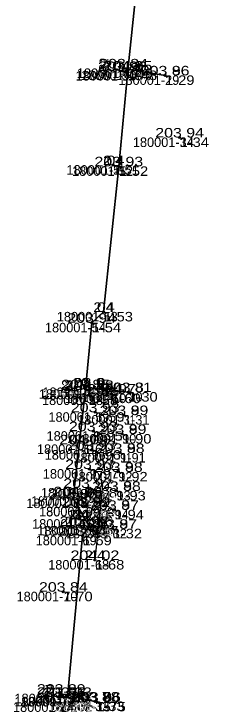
# Model space of a CAD drawing. Extents: x -598473 to -594209, y -1163589 to -1162143.
# Drawn here: x -598473.2 to -598440.8, y -1162504.8 to -1162394.8 of the extents above; entities that cross this region are included whole.
import ezdxf
from ezdxf.enums import TextEntityAlignment as Align

# ---------------------------------------------------------------- set-up
doc = ezdxf.new("R2010")
doc.units = 0
doc.header["$LTSCALE"] = 0.6
doc.header["$PDMODE"] = 32
doc.header["$PDSIZE"] = 0.3
doc.layers.add('1', color=7, linetype='Continuous', lineweight=35)
doc.layers.add('60', color=7, linetype='Continuous', lineweight=25)
for name, color, linetype in [('57', 7, 'Continuous'), ('58', 7, 'Continuous'), ('59', 7, 'Continuous'), ('61', 7, 'Continuous'), ('62', 7, 'Continuous')]:
    doc.layers.add(name, color=color, linetype=linetype)

msp = doc.modelspace()

# ---------------------------------------------------------------- linework, layer by layer
at = {"layer": '1'}
for p, q in [((-598455.95, -1162403.34), (-598449.41, -1162404.44)), ((-598455.28, -1162403.68), (-598456.15, -1162403.75)), ((-598461.93, -1162453.93), (-598461.34, -1162454.04)), ((-598461.36, -1162453.65), (-598455.2, -1162454.38)), ((-598465.77, -1162501.93), (-598460.42, -1162503.16)), ((-598465.77, -1162502.43), (-598464.78, -1162502.45))]:
    msp.add_line(p, q, dxfattribs=at)
for points in [[(-598441.41, -1162294.39), (-598440.77, -1162295.32), (-598444.43, -1162309.35), (-598448.01, -1162329.58), (-598450.14, -1162351.55), (-598449.54, -1162355.6), (-598452.26, -1162382.21), (-598452.85, -1162386.89), (-598453.59, -1162387.55), (-598455.28, -1162403.68), (-598456.7, -1162418.78), (-598459.1, -1162441.73), (-598460.97, -1162443.45), (-598461.93, -1162453.93), (-598463.91, -1162471.16), (-598461.39, -1162475.51), (-598462.43, -1162477.03), (-598464.78, -1162502.45), (-598464.78, -1162502.45)], [(-598461.472, -1162453.735), (-598461.447, -1162453.537), (-598461.249, -1162453.563), (-598461.274, -1162453.761)]]:
    msp.add_lwpolyline(points, dxfattribs=at)
for points in [[(-598455.864, -1162403.451), (-598456.062, -1162403.425), (-598456.037, -1162403.227), (-598455.839, -1162403.253)], [(-598456.064, -1162403.861), (-598456.262, -1162403.835), (-598456.237, -1162403.637), (-598456.039, -1162403.663)], [(-598449.508, -1162404.322), (-598449.31, -1162404.348), (-598449.335, -1162404.546), (-598449.533, -1162404.52)], [(-598461.254, -1162454.151), (-598461.452, -1162454.125), (-598461.427, -1162453.927), (-598461.229, -1162453.953)], [(-598455.295, -1162454.28), (-598455.097, -1162454.306), (-598455.122, -1162454.504), (-598455.32, -1162454.478)], [(-598465.684, -1162502.041), (-598465.882, -1162502.015), (-598465.857, -1162501.817), (-598465.659, -1162501.843)], [(-598465.684, -1162502.541), (-598465.882, -1162502.515), (-598465.857, -1162502.317), (-598465.659, -1162502.343)], [(-598460.513, -1162503.034), (-598460.315, -1162503.06), (-598460.34, -1162503.258), (-598460.538, -1162503.232)]]:
    msp.add_lwpolyline(points, close=True, dxfattribs=at)
msp.add_point((-598458.553, -1162454.51), dxfattribs=at)
at = {"layer": '60'}
msp.add_line((-598459.294, -1162469.09), (-598460.46, -1162480.85), dxfattribs=at)
for p in [(-598456.15, -1162403.75), (-598455.95, -1162403.34), (-598455.28, -1162403.68), (-598449.41, -1162404.44), (-598447.13, -1162414.23), (-598457.58, -1162418.59), (-598456.7, -1162418.78), (-598459.1, -1162441.73), (-598460.97, -1162443.45), (-598461.93, -1162453.93), (-598461.36, -1162453.65), (-598461.34, -1162454.04), (-598455.2, -1162454.38), (-598461.44, -1162454.91), (-598457.86, -1162454.616), (-598460.42, -1162457.55), (-598455.89, -1162458), (-598460.715, -1162460.537), (-598456.187, -1162460.988), (-598462.23, -1162462.62), (-598461.01, -1162463.523), (-598456.483, -1162463.977), (-598461.305, -1162466.51), (-598456.78, -1162466.965), (-598461.6, -1162469.497), (-598463.17, -1162470.8), (-598457.077, -1162469.953), (-598463.91, -1162471.16), (-598461.9, -1162472.45), (-598461.895, -1162472.483), (-598457.373, -1162472.942), (-598462.99, -1162474.41), (-598462.19, -1162475.47), (-598461.39, -1162475.51), (-598457.67, -1162475.93), (-598462.43, -1162477.03), (-598460.46, -1162480.85), (-598465.44, -1162485.85), (-598465.77, -1162501.93), (-598465.77, -1162502.43), (-598464.78, -1162502.45), (-598466, -1162503.3), (-598460.42, -1162503.16), (-598460.22, -1162503.22)]:
    msp.add_point(p, dxfattribs=at)

# ---------------------------------------------------------------- texts
at = {"layer": '1', "width": 0.95}
for s, p in [('R2', (-598458.4405, -1162402.8633)), ('R3', (-598464.3445, -1162453.6168)), ('R4', (-598466.9685, -1162501.5388))]:
    msp.add_text(s, height=1.35, rotation=85, dxfattribs=at).set_placement(p, align=Align.CENTER)
at = {"layer": '57'}
for s, width, p in [('03 9', 1.25, (-598456.1505, -1162403.75)), ('03 8', 1.25, (-598455.95, -1162403.34)), ('04 1', 1.15, (-598455.2795, -1162403.68)), ('03 9', 1.25, (-598449.4105, -1162404.44)), ('03 9', 1.25, (-598447.1305, -1162414.23)), ('2 4', 1.15, (-598457.58, -1162418.59)), ('03 9', 1.25, (-598456.7005, -1162418.78)), ('2 4', 1.15, (-598459.1, -1162441.73)), ('03 9', 1.25, (-598460.9705, -1162443.45)), ('03 8', 1.25, (-598461.93, -1162453.93)), ('03 9', 1.25, (-598461.3605, -1162453.65)), ('03 9', 1.25, (-598461.3405, -1162454.04)), ('2 4', 1.15, (-598457.86, -1162454.616)), ('03 8', 1.25, (-598455.2, -1162454.38)), ('03 9', 1.25, (-598461.4405, -1162454.91)), ('03 9', 1.25, (-598460.4205, -1162457.55)), ('03 9', 1.25, (-598455.8905, -1162458)), ('03 9', 1.25, (-598460.7155, -1162460.537)), ('03 9', 1.25, (-598456.1875, -1162460.988)), ('04 1', 1.15, (-598462.2295, -1162462.62)), ('03 9', 1.25, (-598461.0105, -1162463.523)), ('03 9', 1.25, (-598456.4835, -1162463.977)), ('03 9', 1.25, (-598461.3055, -1162466.51)), ('03 9', 1.25, (-598456.7805, -1162466.965)), ('03 9', 1.25, (-598461.6005, -1162469.497)), ('03 9', 1.25, (-598457.0775, -1162469.953)), ('03 9', 1.25, (-598463.9105, -1162471.16)), ('04 1', 1.15, (-598463.1695, -1162470.8)), ('03 9', 1.25, (-598461.9005, -1162472.45)), ('03 9', 1.25, (-598461.8955, -1162472.483)), ('03 9', 1.25, (-598457.3735, -1162472.942)), ('2 4', 1.15, (-598462.99, -1162474.41)), ('03 9', 1.25, (-598462.1905, -1162475.47)), ('03 8', 1.25, (-598461.39, -1162475.51)), ('03 9', 1.25, (-598457.6705, -1162475.93)), ('03 9', 1.25, (-598462.4305, -1162477.03)), ('2 4', 1.15, (-598460.46, -1162480.85)), ('03 8', 1.25, (-598465.44, -1162485.85)), ('03 9', 1.25, (-598465.7705, -1162501.93)), ('03 8', 1.25, (-598465.77, -1162502.43)), ('03 9', 1.25, (-598464.7805, -1162502.45)), ('03 9', 1.25, (-598466.0005, -1162503.3)), ('03 8', 1.25, (-598460.42, -1162503.16)), ('03 9', 1.25, (-598460.2205, -1162503.22))]:
    msp.add_text(s, height=1.5, dxfattribs=dict(at, width=width)).set_placement(p, align=Align.CENTER)
at = {"layer": '58'}
for s, width, p in [('203 86', 1.25, (-598456.1505, -1162403.75)), ('203 84', 1.25, (-598455.9505, -1162403.34)), ('204 05', 1.25, (-598455.2795, -1162403.68)), ('203 86', 1.25, (-598449.4105, -1162404.44)), ('203 94', 1.25, (-598447.1305, -1162414.23)), ('203 93', 1.25, (-598456.7005, -1162418.78)), (' 04', 1.25, (-598457.58, -1162418.59)), (' 04', 1.25, (-598459.1, -1162441.73)), ('203 94', 1.25, (-598460.9705, -1162443.45)), ('203 85', 1.25, (-598461.9305, -1162453.93)), ('203 88', 1.25, (-598461.3405, -1162454.04)), ('20 .9', 1.15, (-598461.3595, -1162453.65)), ('203 97', 1.25, (-598457.8605, -1162454.616)), ('203 81', 1.2, (-598455.2, -1162454.38)), ('203 92', 1.25, (-598461.4405, -1162454.91)), ('203 93', 1.25, (-598460.4205, -1162457.55)), ('203 89', 1.25, (-598455.89, -1162458)), ('203 93', 1.25, (-598460.7155, -1162460.537)), ('203 89', 1.25, (-598456.187, -1162460.988)), ('204 09', 1.25, (-598462.23, -1162462.62)), ('203 93', 1.25, (-598461.0105, -1162463.523)), ('203 88', 1.25, (-598456.4835, -1162463.977)), ('203 93', 1.25, (-598461.3055, -1162466.51)), ('203 88', 1.25, (-598456.7805, -1162466.965)), ('203 92', 1.25, (-598461.6005, -1162469.497)), ('203 88', 1.25, (-598457.0775, -1162469.953)), ('203 86', 1.25, (-598463.9105, -1162471.16)), ('204 08', 1.25, (-598463.1695, -1162470.8)), ('203 89', 1.25, (-598461.9, -1162472.45)), ('203 92', 1.25, (-598461.8955, -1162472.483)), ('203 87', 1.25, (-598457.3735, -1162472.942)), (' 04', 1.25, (-598462.99, -1162474.41)), ('203 92', 1.25, (-598462.1905, -1162475.47)), ('203 76', 1.25, (-598461.3905, -1162475.51)), ('203 87', 1.25, (-598457.6705, -1162475.93)), ('203 94', 1.25, (-598462.4305, -1162477.03)), ('204 02', 1.25, (-598460.4595, -1162480.85)), ('203 84', 1.25, (-598465.4405, -1162485.85)), ('203 89', 1.25, (-598465.77, -1162501.93)), ('203 85', 1.25, (-598465.7705, -1162502.43)), ('203 93', 1.25, (-598464.7805, -1162502.45)), ('203 91', 1.2, (-598465.9995, -1162503.3)), ('203 78', 1.25, (-598460.4205, -1162503.16)), ('203 86', 1.25, (-598460.2205, -1162503.22))]:
    msp.add_text(s, height=1.5, dxfattribs=dict(at, width=width)).set_placement(p, align=Align.CENTER)
at = {"layer": '59'}
for s, p in [('49', (-598455.95, -1162404.84)), ('50', (-598456.15, -1162405.25)), ('48', (-598455.28, -1162405.18)), ('29', (-598449.41, -1162405.94)), ('34', (-598447.13, -1162415.73)), ('52', (-598456.7, -1162420.28)), ('53', (-598459.1, -1162443.23)), ('54', (-598460.97, -1162444.95)), ('55', (-598461.93, -1162455.43)), ('56', (-598461.36, -1162455.15)), ('57', (-598461.34, -1162455.54)), ('58', (-598461.44, -1162456.41)), ('30', (-598455.2, -1162455.88)), ('59', (-598460.42, -1162459.05)), ('95', (-598460.715, -1162462.037)), ('90', (-598456.187, -1162462.488)), ('96', (-598461.01, -1162465.023)), ('97', (-598461.305, -1162468.01)), ('92', (-598456.78, -1162468.465)), ('98', (-598461.6, -1162470.997)), ('93', (-598457.077, -1162471.453)), ('63', (-598463.91, -1162472.66)), ('62', (-598463.17, -1162472.3)), ('99', (-598461.895, -1162473.983)), ('64', (-598461.9, -1162473.95)), ('94', (-598457.373, -1162474.442)), ('65', (-598462.99, -1162475.91)), ('67', (-598461.39, -1162477.01)), ('32', (-598457.67, -1162477.43)), ('69', (-598462.43, -1162478.53)), ('68', (-598460.46, -1162482.35)), ('70', (-598465.44, -1162487.35)), ('72', (-598465.77, -1162503.43)), ('73', (-598465.77, -1162503.93)), ('74', (-598466, -1162504.8)), ('33', (-598460.42, -1162504.66)), ('75', (-598460.22, -1162504.72))]:
    msp.add_text(s, height=1.5, dxfattribs=at).set_placement(p)
for s, width, p in [('51', 0.8, (-598457.58, -1162420.09)), ('60', 1.05, (-598457.86, -1162456.116)), ('31', 0.8, (-598455.89, -1162459.5)), ('61', 0.85, (-598462.23, -1162464.12)), ('91', 0.8, (-598456.483, -1162465.477)), ('66', 1.05, (-598462.19, -1162476.97)), ('71', 0.8, (-598464.78, -1162503.95))]:
    msp.add_text(s, height=1.5, dxfattribs=dict(at, width=width)).set_placement(p)
at = {"layer": '61'}
for p in [(-598455.95, -1162404.84), (-598456.15, -1162405.25), (-598455.28, -1162405.18), (-598449.41, -1162405.94), (-598447.13, -1162415.73), (-598457.58, -1162420.09), (-598456.7, -1162420.28), (-598459.1, -1162443.23), (-598460.97, -1162444.95), (-598461.93, -1162455.43), (-598461.36, -1162455.15), (-598461.34, -1162455.54), (-598461.44, -1162456.41), (-598457.86, -1162456.116), (-598455.2, -1162455.88), (-598460.42, -1162459.05), (-598455.89, -1162459.5), (-598460.715, -1162462.037), (-598456.187, -1162462.488), (-598462.23, -1162464.12), (-598461.01, -1162465.023), (-598456.483, -1162465.477), (-598461.305, -1162468.01), (-598456.78, -1162468.465), (-598461.6, -1162470.997), (-598457.077, -1162471.453), (-598463.91, -1162472.66), (-598463.17, -1162472.3), (-598461.9, -1162473.95), (-598461.895, -1162473.983), (-598457.373, -1162474.442), (-598462.99, -1162475.91), (-598462.19, -1162476.97), (-598461.39, -1162477.01), (-598457.67, -1162477.43), (-598462.43, -1162478.53), (-598460.46, -1162482.35), (-598465.44, -1162487.35), (-598465.77, -1162503.43), (-598465.77, -1162503.93), (-598464.78, -1162503.95), (-598466, -1162504.8), (-598460.42, -1162504.66), (-598460.22, -1162504.72)]:
    msp.add_text('180001-', height=1.5, dxfattribs=at).set_placement(p, align=Align.RIGHT)
at = {"layer": '62', "width": 1.15}
for s, p in [('1-49', (-598455.95, -1162404.84)), ('1-50', (-598456.15, -1162405.25)), ('1-48', (-598455.28, -1162405.18)), ('1-29', (-598449.41, -1162405.94)), ('1-34', (-598447.13, -1162415.73)), ('1-52', (-598456.7, -1162420.28)), ('1-53', (-598459.1, -1162443.23)), ('1-54', (-598460.97, -1162444.95)), ('1-55', (-598461.93, -1162455.43)), ('1-56', (-598461.36, -1162455.15)), ('1-57', (-598461.34, -1162455.54)), ('1-58', (-598461.44, -1162456.41)), ('1-60', (-598457.86, -1162456.116)), ('1-30', (-598455.2, -1162455.88)), ('1-59', (-598460.42, -1162459.05)), ('1-95', (-598460.715, -1162462.037)), ('1-90', (-598456.187, -1162462.488)), ('1-96', (-598461.01, -1162465.023)), ('1-97', (-598461.305, -1162468.01)), ('1-92', (-598456.78, -1162468.465)), ('1-98', (-598461.6, -1162470.997)), ('1-93', (-598457.077, -1162471.453)), ('1-63', (-598463.91, -1162472.66)), ('1-62', (-598463.17, -1162472.3)), ('1-64', (-598461.9, -1162473.95)), ('1-99', (-598461.895, -1162473.983)), ('1-94', (-598457.373, -1162474.442)), ('1-65', (-598462.99, -1162475.91)), ('1-66', (-598462.19, -1162476.97)), ('1-67', (-598461.39, -1162477.01)), ('1-32', (-598457.67, -1162477.43)), ('1-69', (-598462.43, -1162478.53)), ('1-68', (-598460.46, -1162482.35)), ('1-70', (-598465.44, -1162487.35)), ('1-72', (-598465.77, -1162503.43)), ('1-73', (-598465.77, -1162503.93)), ('1-74', (-598466, -1162504.8)), ('1-33', (-598460.42, -1162504.66)), ('1-75', (-598460.22, -1162504.72))]:
    msp.add_text(s, height=1.5, dxfattribs=at).set_placement(p)
at = {"layer": '62'}
for s, p in [('1-51', (-598457.58, -1162420.09)), ('1-31', (-598455.89, -1162459.5)), ('1-61', (-598462.23, -1162464.12)), ('1-91', (-598456.483, -1162465.477)), ('1-71', (-598464.78, -1162503.95))]:
    msp.add_text(s, height=1.5, dxfattribs=at).set_placement(p)

doc.saveas('drawing.dxf')
